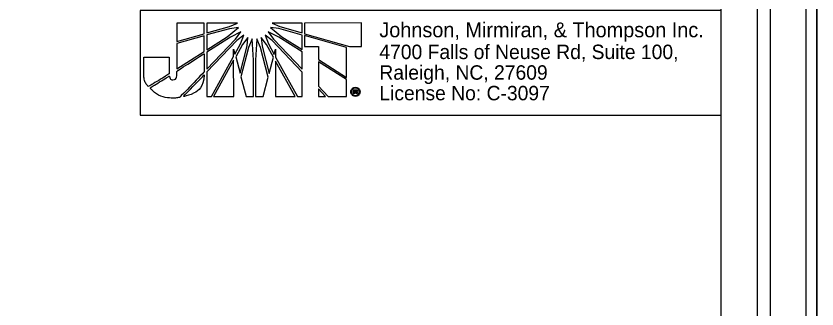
# Model space of a CAD drawing. Extents: x 2294455 to 2294795, y 719276 to 719941.
# Drawn here: x 2294739.4 to 2294794.5, y 719663.1 to 719683.3 of the extents above; entities that cross this region are included whole.
import ezdxf

# ---------------------------------------------------------------- set-up
doc = ezdxf.new("R2010")
doc.units = 0
for name, color, linetype in [('Default', 7, 'Continuous'), ('Old_Level_1', 7, 'Continuous'), ('Old_Level_2', 7, 'Continuous'), ('Sheet Plot Border Inside CELL', 7, 'Continuous'), ('Sheet Plot Border Outside CELL', 7, 'Continuous'), ('Sheet Typical CELL', 7, 'Continuous')]:
    doc.layers.add(name, color=color, linetype=linetype)

msp = doc.modelspace()

# ---------------------------------------------------------------- linework, layer by layer
at = {"layer": 'Default'}
msp.add_lwpolyline([(2294454.524, 719716.169), (2294794.524, 719716.169), (2294794.524, 719496.169), (2294454.524, 719496.169)], close=True, dxfattribs=at)
at = {"layer": 'Old_Level_1'}
for p, q in [((2294752.321, 719682.775), (2294750.449, 719682.773)), ((2294750.449, 719682.773), (2294750.45, 719681.531)), ((2294752.322, 719682.052), (2294752.321, 719682.775)), ((2294754.623, 719682.787), (2294752.516, 719682.785)), ((2294752.516, 719682.785), (2294752.517, 719682.114)), ((2294752.517, 719682.114), (2294754.086, 719682.548)), ((2294754.086, 719682.548), (2294754.623, 719682.787)), ((2294759.084, 719682.782), (2294757.008, 719682.789)), ((2294757.008, 719682.789), (2294757.534, 719682.542)), ((2294757.534, 719682.542), (2294759.085, 719682.108)), ((2294759.085, 719682.108), (2294759.084, 719682.782)), ((2294763.165, 719682.795), (2294759.229, 719682.791)), ((2294759.229, 719682.791), (2294759.23, 719682.068)), ((2294763.167, 719681.182), (2294763.165, 719682.795)), ((2294750.45, 719681.531), (2294752.322, 719682.052)), ((2294754.086, 719682.403), (2294752.517, 719681.969)), ((2294752.517, 719681.969), (2294752.518, 719680.956)), ((2294753.923, 719681.847), (2294754.697, 719682.478)), ((2294754.697, 719682.478), (2294754.086, 719682.403)), ((2294754.852, 719682.188), (2294754.139, 719681.825)), ((2294754.491, 719681.681), (2294754.852, 719682.188)), ((2294755.069, 719681.962), (2294754.572, 719681.579)), ((2294754.841, 719681.363), (2294755.069, 719681.962)), ((2294756.521, 719681.964), (2294756.75, 719681.364)), ((2294757.018, 719681.581), (2294756.521, 719681.964)), ((2294756.74, 719682.189), (2294757.102, 719681.674)), ((2294757.463, 719681.829), (2294756.74, 719682.189)), ((2294756.903, 719682.48), (2294757.689, 719681.838)), ((2294757.481, 719682.406), (2294756.903, 719682.48)), ((2294759.085, 719681.966), (2294757.481, 719682.406)), ((2294759.074, 719680.974), (2294759.085, 719681.966)), ((2294759.23, 719682.068), (2294759.23, 719682.047)), ((2294759.23, 719682.047), (2294762.33, 719681.181)), ((2294759.23, 719681.935), (2294759.23, 719681.923)), ((2294762.132, 719681.11), (2294759.23, 719681.935)), ((2294752.322, 719681.916), (2294750.45, 719681.389)), ((2294750.45, 719681.389), (2294750.452, 719679.644)), ((2294752.323, 719680.832), (2294752.322, 719681.916)), ((2294752.518, 719680.956), (2294753.923, 719681.847)), ((2294754.139, 719681.825), (2294752.518, 719680.792)), ((2294752.519, 719679.624), (2294754.491, 719681.681)), ((2294754.572, 719681.579), (2294752.519, 719679.426)), ((2294755.338, 719681.796), (2294754.967, 719681.32)), ((2294755.286, 719681.218), (2294755.338, 719681.796)), ((2294755.647, 719681.713), (2294755.391, 719681.113)), ((2294755.728, 719680.236), (2294755.647, 719681.713)), ((2294755.956, 719681.713), (2294755.861, 719680.236)), ((2294756.203, 719681.114), (2294755.956, 719681.713)), ((2294756.255, 719681.797), (2294756.318, 719681.197)), ((2294756.617, 719681.321), (2294756.255, 719681.797)), ((2294759.075, 719679.414), (2294757.018, 719681.581)), ((2294757.102, 719681.674), (2294759.075, 719679.609)), ((2294759.074, 719680.807), (2294757.463, 719681.829)), ((2294757.689, 719681.838), (2294759.074, 719680.974)), ((2294759.23, 719681.923), (2294759.231, 719681.169)), ((2294750.452, 719679.644), (2294752.323, 719680.832)), ((2294754.356, 719680.494), (2294754.356, 719680.988)), ((2294754.356, 719680.988), (2294754.449, 719680.649)), ((2294754.449, 719680.649), (2294754.841, 719681.363)), ((2294754.967, 719681.32), (2294754.502, 719680.473)), ((2294754.802, 719679.348), (2294755.286, 719681.218)), ((2294755.391, 719681.113), (2294754.864, 719679.089)), ((2294756.743, 719679.06), (2294756.203, 719681.114)), ((2294756.318, 719681.197), (2294756.804, 719679.307)), ((2294757.103, 719680.444), (2294756.617, 719681.321)), ((2294756.75, 719681.364), (2294757.152, 719680.62)), ((2294757.152, 719680.62), (2294757.248, 719680.991)), ((2294757.248, 719680.991), (2294757.248, 719680.444)), ((2294759.231, 719681.169), (2294760.192, 719681.17)), ((2294760.192, 719681.17), (2294760.193, 719680.271)), ((2294762.134, 719679.043), (2294762.132, 719681.11)), ((2294762.33, 719681.181), (2294763.167, 719681.182)), ((2294752.518, 719680.792), (2294752.519, 719679.624)), ((2294752.83, 719677.728), (2294754.356, 719680.494)), ((2294754.502, 719680.473), (2294754.802, 719679.348)), ((2294756.804, 719679.307), (2294757.103, 719680.444)), ((2294757.248, 719680.444), (2294758.746, 719677.733)), ((2294759.075, 719679.609), (2294759.074, 719680.807)), ((2294754.357, 719680.225), (2294752.975, 719677.728)), ((2294754.371, 719677.729), (2294754.357, 719680.225)), ((2294755.731, 719677.739), (2294755.728, 719680.236)), ((2294755.861, 719680.236), (2294755.864, 719677.74)), ((2294758.592, 719677.742), (2294757.248, 719680.175)), ((2294757.248, 719680.175), (2294757.251, 719677.741)), ((2294760.193, 719680.271), (2294762.134, 719679.043)), ((2294760.193, 719680.116), (2294760.194, 719678.442)), ((2294762.134, 719678.898), (2294760.193, 719680.116)), ((2294752.519, 719679.426), (2294752.521, 719677.727)), ((2294759.077, 719677.733), (2294759.075, 719679.414)), ((2294754.864, 719679.089), (2294755.218, 719677.739)), ((2294756.383, 719677.74), (2294756.743, 719679.06)), ((2294762.135, 719677.736), (2294762.134, 719678.898)), ((2294760.194, 719678.442), (2294760.866, 719677.735)), ((2294760.68, 719677.735), (2294760.195, 719678.26)), ((2294760.195, 719678.26), (2294760.195, 719677.735)), ((2294762.628, 719677.914), (2294762.628, 719678.2)), ((2294762.628, 719678.2), (2294762.745, 719678.2)), ((2294762.745, 719678.145), (2294762.693, 719678.145)), ((2294762.693, 719678.145), (2294762.693, 719678.077)), ((2294762.693, 719678.077), (2294762.745, 719678.078)), ((2294762.745, 719678.369), (2294762.745, 719678.309)), ((2294762.745, 719678.309), (2294762.745, 719678.369)), ((2294762.745, 719678.2), (2294762.745, 719678.145)), ((2294762.745, 719678.145), (2294762.745, 719678.2)), ((2294762.745, 719678.2), (2294762.763, 719678.2)), ((2294762.753, 719678.145), (2294762.745, 719678.145)), ((2294762.745, 719678.078), (2294762.745, 719678.026)), ((2294762.745, 719678.026), (2294762.745, 719678.078)), ((2294762.745, 719678.078), (2294762.748, 719678.078)), ((2294752.521, 719677.727), (2294752.83, 719677.728)), ((2294752.975, 719677.728), (2294754.371, 719677.729)), ((2294755.218, 719677.739), (2294755.731, 719677.739)), ((2294755.864, 719677.74), (2294756.383, 719677.74)), ((2294757.251, 719677.741), (2294758.592, 719677.742)), ((2294758.746, 719677.733), (2294759.077, 719677.733)), ((2294760.195, 719677.735), (2294760.68, 719677.735)), ((2294760.866, 719677.735), (2294762.135, 719677.736)), ((2294762.693, 719677.914), (2294762.628, 719677.914)), ((2294762.745, 719678.026), (2294762.693, 719678.025)), ((2294762.693, 719678.025), (2294762.693, 719677.914)), ((2294762.748, 719678.026), (2294762.745, 719678.026)), ((2294762.745, 719677.802), (2294762.745, 719677.739)), ((2294762.745, 719677.739), (2294762.745, 719677.802)), ((2294762.745, 719677.802), (2294762.748, 719677.802)), ((2294762.748, 719677.739), (2294762.745, 719677.739))]:
    msp.add_line(p, q, dxfattribs=at)
msp.add_lwpolyline([(2294747.917, 719676.44), (2294787.924, 719676.44), (2294787.924, 719683.659), (2294747.917, 719683.659)], close=True, dxfattribs=at)
for points in [[(2294750.45, 719681.531), (2294752.322, 719682.052), (2294752.321, 719682.775), (2294750.449, 719682.773), (2294750.45, 719681.531)], [(2294754.086, 719682.548), (2294754.623, 719682.787), (2294752.516, 719682.785), (2294752.517, 719682.114), (2294754.086, 719682.548)], [(2294757.534, 719682.542), (2294759.085, 719682.108), (2294759.084, 719682.782), (2294757.008, 719682.789), (2294757.534, 719682.542)], [(2294763.165, 719682.795), (2294759.229, 719682.791), (2294759.23, 719682.068), (2294759.23, 719682.047), (2294762.33, 719681.181), (2294763.167, 719681.182), (2294763.165, 719682.795)], [(2294752.517, 719681.969), (2294752.518, 719680.956), (2294753.923, 719681.847), (2294754.697, 719682.478), (2294754.086, 719682.403), (2294752.517, 719681.969)], [(2294752.518, 719680.792), (2294752.519, 719679.624), (2294754.491, 719681.681), (2294754.852, 719682.188), (2294754.139, 719681.825), (2294752.518, 719680.792)], [(2294755.069, 719681.962), (2294754.572, 719681.579), (2294752.519, 719679.426), (2294752.521, 719677.727), (2294752.83, 719677.728), (2294754.356, 719680.494), (2294754.356, 719680.988), (2294754.449, 719680.649), (2294754.841, 719681.363), (2294755.069, 719681.962)], [(2294756.521, 719681.964), (2294756.75, 719681.364), (2294757.152, 719680.62), (2294757.248, 719680.991), (2294757.248, 719680.444), (2294758.746, 719677.733), (2294759.077, 719677.733), (2294759.075, 719679.414), (2294757.018, 719681.581), (2294756.521, 719681.964)], [(2294756.74, 719682.189), (2294757.102, 719681.674), (2294759.075, 719679.609), (2294759.074, 719680.807), (2294757.463, 719681.829), (2294756.74, 719682.189)], [(2294756.903, 719682.48), (2294757.689, 719681.838), (2294759.074, 719680.974), (2294759.085, 719681.966), (2294757.481, 719682.406), (2294756.903, 719682.48)], [(2294759.23, 719681.935), (2294759.23, 719681.923), (2294759.231, 719681.169), (2294760.192, 719681.17), (2294760.193, 719680.271), (2294762.134, 719679.043), (2294762.132, 719681.11), (2294759.23, 719681.935)], [(2294750.452, 719679.644), (2294752.323, 719680.832), (2294752.322, 719681.916), (2294750.45, 719681.389), (2294750.452, 719679.644)], [(2294755.338, 719681.796), (2294754.967, 719681.32), (2294754.502, 719680.473), (2294754.802, 719679.348), (2294755.286, 719681.218), (2294755.338, 719681.796)], [(2294755.391, 719681.113), (2294754.864, 719679.089), (2294755.218, 719677.739), (2294755.731, 719677.739), (2294755.728, 719680.236), (2294755.647, 719681.713), (2294755.391, 719681.113)], [(2294755.956, 719681.713), (2294755.861, 719680.236), (2294755.864, 719677.74), (2294756.383, 719677.74), (2294756.743, 719679.06), (2294756.203, 719681.114), (2294755.956, 719681.713)], [(2294756.255, 719681.797), (2294756.318, 719681.197), (2294756.804, 719679.307), (2294757.103, 719680.444), (2294756.617, 719681.321), (2294756.255, 719681.797)], [(2294752.975, 719677.728), (2294754.371, 719677.729), (2294754.357, 719680.225), (2294752.975, 719677.728)], [(2294757.251, 719677.741), (2294758.592, 719677.742), (2294757.248, 719680.175), (2294757.251, 719677.741)], [(2294760.193, 719680.116), (2294760.194, 719678.442), (2294760.866, 719677.735), (2294762.135, 719677.736), (2294762.134, 719678.898), (2294760.193, 719680.116), (2294760.193, 719680.116)], [(2294760.195, 719677.735), (2294760.195, 719677.735), (2294760.68, 719677.735), (2294760.195, 719678.26), (2294760.195, 719677.735)], [(2294762.87, 719677.981), (2294762.87, 719677.966), (2294762.873, 719677.955), (2294762.873, 719677.945), (2294762.88, 719677.914), (2294762.821, 719677.914)]]:
    msp.add_lwpolyline(points, dxfattribs=at)
for points, degree in [([(2294749.914, 719680.447), (2294749.914, 719680.447), (2294748.18, 719680.445), (2294748.18, 719680.445), (2294748.18, 719680.445), (2294748.181, 719679.361), (2294748.181, 719679.361), (2294748.181, 719679.361), (2294748.182, 719679.246), (2294748.182, 719679.246), (2294748.182, 719678.906), (2294748.293, 719678.638), (2294748.491, 719678.412), (2294748.491, 719678.412), (2294749.915, 719679.279), (2294749.915, 719679.3), (2294749.915, 719679.3), (2294749.914, 719680.447), (2294749.914, 719680.447)], 3), ([(2294750.184, 719678.887), (2294750.073, 719678.886), (2294749.977, 719678.948), (2294749.937, 719679.155), (2294749.937, 719679.155), (2294748.593, 719678.323), (2294748.593, 719678.323), (2294749.008, 719677.888), (2294749.669, 719677.629), (2294750.228, 719677.629), (2294750.374, 719677.629), (2294750.485, 719677.642), (2294750.639, 719677.673), (2294750.639, 719677.673), (2294752.324, 719679.417), (2294752.324, 719679.417), (2294752.324, 719679.417), (2294752.323, 719680.677), (2294752.323, 719680.677), (2294752.323, 719680.677), (2294750.452, 719679.486), (2294750.452, 719679.486), (2294750.453, 719679.014), (2294750.338, 719678.887), (2294750.184, 719678.887)], 3), ([(2294750.184, 719678.887), (2294750.073, 719678.886), (2294749.977, 719678.948), (2294749.937, 719679.155), (2294749.937, 719679.155), (2294748.593, 719678.323), (2294748.593, 719678.323), (2294749.008, 719677.888), (2294749.669, 719677.629), (2294750.228, 719677.629), (2294750.374, 719677.629), (2294750.485, 719677.642), (2294750.639, 719677.673), (2294750.639, 719677.673), (2294752.324, 719679.417), (2294752.324, 719679.417), (2294752.324, 719679.417), (2294752.323, 719680.677), (2294752.323, 719680.677), (2294752.323, 719680.677), (2294750.452, 719679.486), (2294750.452, 719679.486), (2294750.453, 719679.014), (2294750.338, 719678.887), (2294750.184, 719678.887)], 3), ([(2294752.325, 719679.219), (2294752.325, 719679.219), (2294750.868, 719677.713), (2294750.868, 719677.713), (2294751.581, 719677.89), (2294752.291, 719678.363), (2294752.325, 719679.219)], 3), ([(2294762.745, 719677.739), (2294762.66, 719677.739), (2294762.584, 719677.77), (2294762.521, 719677.833), (2294762.459, 719677.893), (2294762.428, 719677.968), (2294762.428, 719678.056), (2294762.428, 719678.145), (2294762.459, 719678.22), (2294762.521, 719678.278), (2294762.583, 719678.338), (2294762.656, 719678.369), (2294762.745, 719678.369)], 3), ([(2294762.745, 719678.309), (2294762.675, 719678.309), (2294762.615, 719678.286), (2294762.565, 719678.239), (2294762.516, 719678.189), (2294762.49, 719678.127), (2294762.49, 719678.057), (2294762.49, 719677.986), (2294762.516, 719677.924), (2294762.566, 719677.874), (2294762.615, 719677.825), (2294762.675, 719677.802), (2294762.745, 719677.802)], 3), ([(2294762.745, 719678.369), (2294762.833, 719678.369), (2294762.909, 719678.338), (2294762.971, 719678.278), (2294763.034, 719678.221), (2294763.065, 719678.146), (2294763.065, 719678.057)], 3), ([(2294762.748, 719677.802), (2294762.818, 719677.802), (2294762.878, 719677.825), (2294762.927, 719677.875), (2294762.977, 719677.924), (2294763.003, 719677.987), (2294763.003, 719678.057), (2294763.003, 719678.127), (2294762.976, 719678.19), (2294762.927, 719678.239), (2294762.878, 719678.286), (2294762.818, 719678.309), (2294762.745, 719678.309)], 3), ([(2294762.748, 719678.078), (2294762.789, 719678.078), (2294762.81, 719678.091), (2294762.81, 719678.114), (2294762.81, 719678.135), (2294762.792, 719678.145), (2294762.753, 719678.145)], 3), ([(2294762.763, 719678.2), (2294762.836, 719678.2), (2294762.872, 719678.171), (2294762.872, 719678.114), (2294762.872, 719678.088), (2294762.862, 719678.067), (2294762.839, 719678.052)], 3), ([(2294763.065, 719678.057), (2294763.065, 719677.969), (2294763.034, 719677.893), (2294762.974, 719677.831), (2294762.912, 719677.771), (2294762.836, 719677.739), (2294762.748, 719677.739)], 3), ([(2294762.797, 719678.015), (2294762.789, 719678.02), (2294762.774, 719678.026), (2294762.748, 719678.026)], 2), ([(2294762.821, 719677.914), (2294762.813, 719677.929), (2294762.808, 719677.945), (2294762.808, 719677.966), (2294762.808, 719677.992), (2294762.805, 719678.007), (2294762.797, 719678.015)], 3), ([(2294762.839, 719678.052), (2294762.857, 719678.041), (2294762.867, 719678.018), (2294762.87, 719677.981)], 2)]:
    msp.add_open_spline(points, degree=degree, dxfattribs=at)
at = {"layer": 'Old_Level_2'}
msp.add_line((2294794.524, 719716.169), (2294794.524, 719496.169), dxfattribs=at)
at = {"layer": 'Sheet Plot Border Inside CELL'}
msp.add_lwpolyline([(2294790.424, 719711.679), (2294457.124, 719711.679), (2294457.124, 719500.659), (2294790.424, 719500.659)], close=True, dxfattribs=at)
at = {"layer": 'Sheet Plot Border Outside CELL'}
for points in [[(2294793.79, 719718.758), (2294456.99, 719718.758), (2294456.99, 719498.758), (2294793.79, 719498.758)], [(2294454.524, 719496.169), (2294791.324, 719496.169), (2294791.324, 719716.169), (2294454.524, 719716.169)], [(2294794.524, 719716.169), (2294454.524, 719716.169), (2294454.524, 719496.169), (2294794.524, 719496.169)]]:
    msp.add_lwpolyline(points, close=True, dxfattribs=at)
at = {"layer": 'Sheet Typical CELL'}
msp.add_lwpolyline([(2294787.924, 719711.169), (2294487.924, 719711.169), (2294487.924, 719501.169), (2294787.924, 719501.169)], close=True, dxfattribs=at)

# ---------------------------------------------------------------- texts
at = {"layer": 'Old_Level_1'}
for s, height, p in [('Johnson, Mirmiran, & Thompson Inc.', 1.02224, (2294764.393, 719681.81)), ('4700 Falls of Neuse Rd, Suite 100, ', 0.99303, (2294764.393, 719680.31)), ('Raleigh, NC, 27609', 0.99303, (2294764.393, 719678.891)), ('License No: C-3097', 0.99303, (2294764.393, 719677.472))]:
    msp.add_text(s, height=height, dxfattribs=at).set_placement(p)

doc.saveas('drawing.dxf')
